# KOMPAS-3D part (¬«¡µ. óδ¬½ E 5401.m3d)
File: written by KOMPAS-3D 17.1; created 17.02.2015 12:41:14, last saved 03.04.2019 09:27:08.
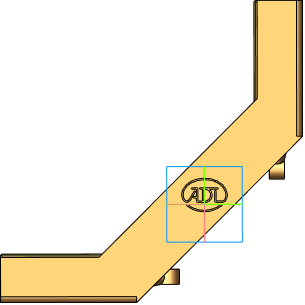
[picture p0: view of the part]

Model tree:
1. Операция без истории:3  (labels: Сталь 20  ГОСТ 1050-88)

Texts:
  Толщина листового тела
  Глубина освобождения сгиба
  Ширина освобождения сгиба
